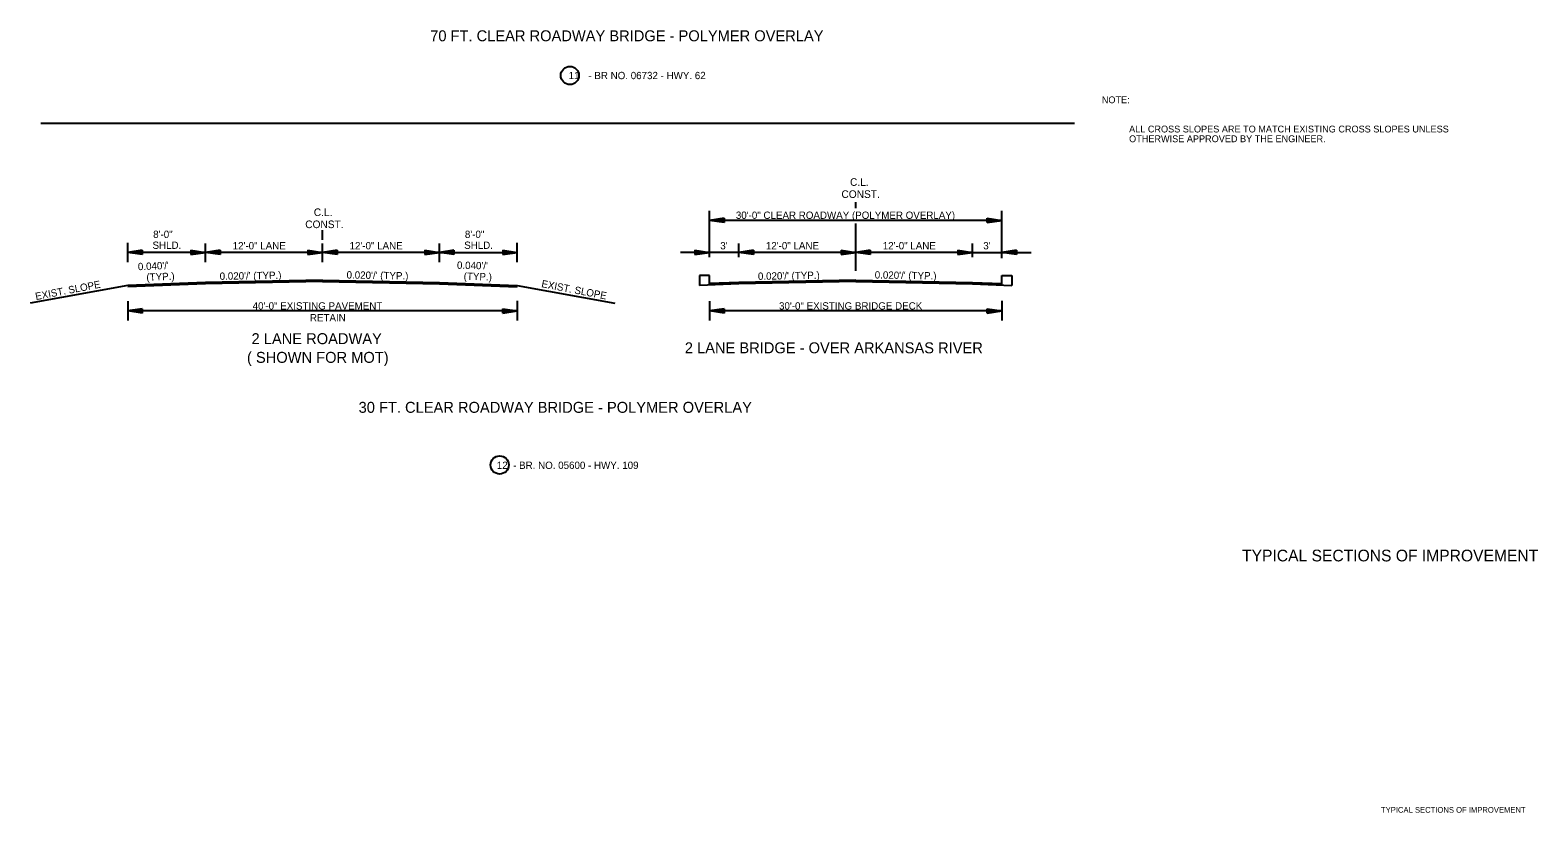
# Model space of a CAD drawing. Extents: x 550980 to 1930787, y -1972975 to 596640.
# Drawn here: x 550998 to 552546, y -1950690 to -1949887 of the extents above; entities that cross this region are included whole.
import ezdxf

# ---------------------------------------------------------------- set-up
doc = ezdxf.new("R2010")
doc.units = 0
for name, color, linetype in [('R_Border', 7, 'Continuous'), ('R_Border Notes', 7, 'Continuous'), ('R_Draft', 7, 'Continuous'), ('S_AREA_CALC', 7, 'Continuous')]:
    doc.layers.add(name, color=color, linetype=linetype)

# ---------------------------------------------------------------- blocks, each defined once
blk = doc.blocks.new('BPPOLY')
at = {"layer": 'R_Border'}
blk.add_circle((0, 0), 9.34, dxfattribs=at)

msp = doc.modelspace()

# ---------------------------------------------------------------- linework, layer by layer
at = {"layer": 'R_Border'}
for p, q in [((551009, -1949982.4), (552070.2, -1949982.4)), ((551685.4, -1950138.7), (551685.4, -1950148.8)), ((551695.6, -1950138.7), (551685.4, -1950138.7)), ((551695.6, -1950148.1), (551695.6, -1950138.7)), ((551995.6, -1950148.1), (551995.6, -1950138.7)), ((551995.6, -1950138.7), (552005.8, -1950138.7)), ((552005.8, -1950138.7), (552005.8, -1950148.8))]:
    msp.add_line(p, q, dxfattribs=at)
msp.add_circle((551480.1, -1950333.1), 9.34, dxfattribs=at)
at = {"layer": 'R_Draft'}
for p, q in [((551845.6, -1950069.4), (551845.6, -1950063.3)), ((551695.6, -1950119.7), (551695.6, -1950072.2)), ((551710.6, -1950079.9), (551695.6, -1950082.1)), ((551995.6, -1950082.1), (551695.6, -1950082.1)), ((551710.6, -1950084.4), (551695.6, -1950082.1)), ((551710.6, -1950080.2), (551698.1, -1950082.1)), ((551710.6, -1950084), (551698.1, -1950082.1)), ((551710.6, -1950080.6), (551700.7, -1950082.1)), ((551710.6, -1950083.6), (551700.7, -1950082.1)), ((551710.6, -1950081), (551703.2, -1950082.1)), ((551710.6, -1950083.2), (551703.2, -1950082.1)), ((551710.6, -1950081.4), (551705.7, -1950082.1)), ((551710.6, -1950082.9), (551705.7, -1950082.1)), ((551710.6, -1950081.8), (551708.2, -1950082.1)), ((551710.6, -1950082.5), (551708.2, -1950082.1)), ((551710.6, -1950079.9), (551710.6, -1950084.4)), ((551980.6, -1950079.9), (551995.6, -1950082.1)), ((551980.6, -1950084.4), (551980.6, -1950079.9)), ((551980.6, -1950080.2), (551993.1, -1950082.1)), ((551980.6, -1950080.6), (551990.5, -1950082.1)), ((551980.6, -1950081), (551988, -1950082.1)), ((551980.6, -1950081.4), (551985.5, -1950082.1)), ((551980.6, -1950081.8), (551983, -1950082.1)), ((551980.6, -1950084.4), (551995.6, -1950082.1)), ((551980.6, -1950082.9), (551985.5, -1950082.1)), ((551980.6, -1950083.6), (551990.5, -1950082.1)), ((551980.6, -1950084), (551993.1, -1950082.1)), ((551980.6, -1950083.2), (551988, -1950082.1)), ((551980.6, -1950082.5), (551983, -1950082.1)), ((551995.6, -1950120.9), (551995.6, -1950072.2)), ((551298.2, -1950101.9), (551298.2, -1950092)), ((551845.6, -1950105.8), (551845.6, -1950085.3)), ((551098.2, -1950125), (551098.2, -1950105)), ((551113.2, -1950112.7), (551098.2, -1950115)), ((551113.2, -1950113.1), (551100.7, -1950115)), ((551113.2, -1950112.7), (551113.2, -1950117.2)), ((551163.2, -1950112.7), (551178.2, -1950115)), ((551163.2, -1950112.7), (551163.2, -1950117.2)), ((551163.2, -1950113.1), (551175.6, -1950115)), ((551178.2, -1950125), (551178.2, -1950105.8)), ((551193.2, -1950112.7), (551178.2, -1950115)), ((551193.2, -1950113.1), (551180.7, -1950115)), ((551193.2, -1950112.7), (551193.2, -1950117.2)), ((551283.2, -1950112.7), (551298.2, -1950115)), ((551283.2, -1950112.7), (551283.2, -1950117.2)), ((551283.2, -1950113.1), (551295.6, -1950115)), ((551298.2, -1950125), (551298.2, -1950105.8)), ((551313.2, -1950112.7), (551298.2, -1950115)), ((551313.2, -1950113.1), (551300.7, -1950115)), ((551313.2, -1950112.7), (551313.2, -1950117.2)), ((551403.2, -1950112.7), (551418.2, -1950115)), ((551403.2, -1950112.7), (551403.2, -1950117.2)), ((551403.2, -1950113.1), (551415.6, -1950115)), ((551418.2, -1950125), (551418.2, -1950105.8)), ((551433.2, -1950112.7), (551418.2, -1950115)), ((551433.2, -1950113.1), (551420.7, -1950115)), ((551433.2, -1950112.7), (551433.2, -1950117.2)), ((551483.2, -1950112.7), (551498.2, -1950115)), ((551483.2, -1950112.7), (551483.2, -1950117.2)), ((551483.2, -1950113.1), (551495.6, -1950115)), ((551498.2, -1950125), (551498.2, -1950105)), ((551680.6, -1950112.7), (551695.6, -1950115)), ((551680.6, -1950112.7), (551680.6, -1950117.2)), ((551680.6, -1950113.1), (551693.1, -1950115)), ((551725.6, -1950119.7), (551725.6, -1950105.8)), ((551740.6, -1950112.7), (551725.6, -1950115)), ((551740.6, -1950113.1), (551728.1, -1950115)), ((551740.6, -1950112.7), (551740.6, -1950117.2)), ((551830.6, -1950112.7), (551845.6, -1950115)), ((551830.6, -1950112.7), (551830.6, -1950117.2)), ((551830.6, -1950113.1), (551843.1, -1950115)), ((551845.6, -1950133.7), (551845.6, -1950105.8)), ((551860.6, -1950112.7), (551845.6, -1950115)), ((551860.6, -1950113.1), (551848.1, -1950115)), ((551860.6, -1950112.7), (551860.6, -1950117.2)), ((551950.6, -1950112.7), (551965.6, -1950115)), ((551950.6, -1950112.7), (551950.6, -1950117.2)), ((551950.6, -1950113.1), (551963.1, -1950115)), ((551965.6, -1950119.7), (551965.6, -1950105.8)), ((552010.6, -1950112.7), (551995.6, -1950115)), ((552010.6, -1950113.1), (551998.1, -1950115)), ((552010.6, -1950112.7), (552010.6, -1950117.2)), ((551178.2, -1950115), (551098.2, -1950115)), ((551113.2, -1950117.2), (551098.2, -1950115)), ((551113.2, -1950116.8), (551100.7, -1950115)), ((551113.2, -1950113.5), (551103.2, -1950115)), ((551113.2, -1950116.5), (551103.2, -1950115)), ((551113.2, -1950113.8), (551105.7, -1950115)), ((551113.2, -1950116.1), (551105.7, -1950115)), ((551113.2, -1950114.2), (551108.3, -1950115)), ((551113.2, -1950115.7), (551108.3, -1950115)), ((551113.2, -1950114.6), (551110.8, -1950115)), ((551113.2, -1950115.3), (551110.8, -1950115)), ((551163.2, -1950113.5), (551173.1, -1950115)), ((551163.2, -1950113.8), (551170.6, -1950115)), ((551163.2, -1950114.2), (551168, -1950115)), ((551163.2, -1950114.6), (551165.5, -1950115)), ((551163.2, -1950117.2), (551178.2, -1950115)), ((551163.2, -1950115.7), (551168, -1950115)), ((551163.2, -1950116.5), (551173.1, -1950115)), ((551163.2, -1950116.8), (551175.6, -1950115)), ((551163.2, -1950116.1), (551170.6, -1950115)), ((551163.2, -1950115.3), (551165.5, -1950115)), ((551298.2, -1950115), (551178.2, -1950115)), ((551193.2, -1950117.2), (551178.2, -1950115)), ((551193.2, -1950116.8), (551180.7, -1950115)), ((551193.2, -1950113.5), (551183.2, -1950115)), ((551193.2, -1950116.5), (551183.2, -1950115)), ((551193.2, -1950113.8), (551185.7, -1950115)), ((551193.2, -1950116.1), (551185.7, -1950115)), ((551193.2, -1950114.2), (551188.3, -1950115)), ((551193.2, -1950115.7), (551188.3, -1950115)), ((551193.2, -1950114.6), (551190.8, -1950115)), ((551193.2, -1950115.3), (551190.8, -1950115)), ((551283.2, -1950113.5), (551293.1, -1950115)), ((551283.2, -1950113.8), (551290.6, -1950115)), ((551283.2, -1950114.2), (551288, -1950115)), ((551283.2, -1950114.6), (551285.5, -1950115)), ((551283.2, -1950117.2), (551298.2, -1950115)), ((551283.2, -1950115.7), (551288, -1950115)), ((551283.2, -1950116.5), (551293.1, -1950115)), ((551283.2, -1950116.8), (551295.6, -1950115)), ((551283.2, -1950116.1), (551290.6, -1950115)), ((551283.2, -1950115.3), (551285.5, -1950115)), ((551418.2, -1950115), (551298.2, -1950115)), ((551313.2, -1950117.2), (551298.2, -1950115)), ((551313.2, -1950116.8), (551300.7, -1950115)), ((551313.2, -1950113.5), (551303.2, -1950115)), ((551313.2, -1950116.5), (551303.2, -1950115)), ((551313.2, -1950113.8), (551305.7, -1950115)), ((551313.2, -1950116.1), (551305.7, -1950115)), ((551313.2, -1950114.2), (551308.3, -1950115)), ((551313.2, -1950115.7), (551308.3, -1950115)), ((551313.2, -1950114.6), (551310.8, -1950115)), ((551313.2, -1950115.3), (551310.8, -1950115)), ((551403.2, -1950113.5), (551413.1, -1950115)), ((551403.2, -1950113.8), (551410.6, -1950115)), ((551403.2, -1950114.2), (551408, -1950115)), ((551403.2, -1950114.6), (551405.5, -1950115)), ((551403.2, -1950117.2), (551418.2, -1950115)), ((551403.2, -1950115.7), (551408, -1950115)), ((551403.2, -1950116.5), (551413.1, -1950115)), ((551403.2, -1950116.8), (551415.6, -1950115)), ((551403.2, -1950116.1), (551410.6, -1950115)), ((551403.2, -1950115.3), (551405.5, -1950115)), ((551418.2, -1950115), (551498.2, -1950115)), ((551433.2, -1950117.2), (551418.2, -1950115)), ((551433.2, -1950116.8), (551420.7, -1950115)), ((551433.2, -1950113.5), (551423.2, -1950115)), ((551433.2, -1950116.5), (551423.2, -1950115)), ((551433.2, -1950113.8), (551425.7, -1950115)), ((551433.2, -1950116.1), (551425.7, -1950115)), ((551433.2, -1950114.2), (551428.3, -1950115)), ((551433.2, -1950115.7), (551428.3, -1950115)), ((551433.2, -1950114.6), (551430.8, -1950115)), ((551433.2, -1950115.3), (551430.8, -1950115)), ((551483.2, -1950113.5), (551493.1, -1950115)), ((551483.2, -1950113.8), (551490.6, -1950115)), ((551483.2, -1950114.2), (551488, -1950115)), ((551483.2, -1950114.6), (551485.5, -1950115)), ((551483.2, -1950117.2), (551498.2, -1950115)), ((551483.2, -1950115.7), (551488, -1950115)), ((551483.2, -1950116.5), (551493.1, -1950115)), ((551483.2, -1950116.8), (551495.6, -1950115)), ((551483.2, -1950116.1), (551490.6, -1950115)), ((551483.2, -1950115.3), (551485.5, -1950115)), ((551695.6, -1950115), (551665.6, -1950115)), ((551680.6, -1950113.5), (551690.5, -1950115)), ((551680.6, -1950113.8), (551688, -1950115)), ((551680.6, -1950114.2), (551685.5, -1950115)), ((551680.6, -1950114.6), (551683, -1950115)), ((551680.6, -1950117.2), (551695.6, -1950115)), ((551680.6, -1950115.7), (551685.5, -1950115)), ((551680.6, -1950116.5), (551690.5, -1950115)), ((551680.6, -1950116.8), (551693.1, -1950115)), ((551680.6, -1950116.1), (551688, -1950115)), ((551680.6, -1950115.3), (551683, -1950115)), ((551725.6, -1950115), (551695.6, -1950115)), ((551845.6, -1950115), (551725.6, -1950115)), ((551740.6, -1950117.2), (551725.6, -1950115)), ((551740.6, -1950116.8), (551728.1, -1950115)), ((551740.6, -1950113.5), (551730.7, -1950115)), ((551740.6, -1950116.5), (551730.7, -1950115)), ((551740.6, -1950113.8), (551733.2, -1950115)), ((551740.6, -1950116.1), (551733.2, -1950115)), ((551740.6, -1950114.2), (551735.7, -1950115)), ((551740.6, -1950115.7), (551735.7, -1950115)), ((551740.6, -1950114.6), (551738.2, -1950115)), ((551740.6, -1950115.3), (551738.2, -1950115)), ((551830.6, -1950113.5), (551840.5, -1950115)), ((551830.6, -1950113.8), (551838, -1950115)), ((551830.6, -1950114.2), (551835.5, -1950115)), ((551830.6, -1950114.6), (551833, -1950115)), ((551830.6, -1950117.2), (551845.6, -1950115)), ((551830.6, -1950115.7), (551835.5, -1950115)), ((551830.6, -1950116.5), (551840.5, -1950115)), ((551830.6, -1950116.8), (551843.1, -1950115)), ((551830.6, -1950116.1), (551838, -1950115)), ((551830.6, -1950115.3), (551833, -1950115)), ((551965.6, -1950115), (551845.6, -1950115)), ((551860.6, -1950117.2), (551845.6, -1950115)), ((551860.6, -1950116.8), (551848.1, -1950115)), ((551860.6, -1950113.5), (551850.7, -1950115)), ((551860.6, -1950116.5), (551850.7, -1950115)), ((551860.6, -1950113.8), (551853.2, -1950115)), ((551860.6, -1950116.1), (551853.2, -1950115)), ((551860.6, -1950114.2), (551855.7, -1950115)), ((551860.6, -1950115.7), (551855.7, -1950115)), ((551860.6, -1950114.6), (551858.2, -1950115)), ((551860.6, -1950115.3), (551858.2, -1950115)), ((551950.6, -1950113.5), (551960.5, -1950115)), ((551950.6, -1950113.8), (551958, -1950115)), ((551950.6, -1950114.2), (551955.5, -1950115)), ((551950.6, -1950114.6), (551953, -1950115)), ((551950.6, -1950117.2), (551965.6, -1950115)), ((551950.6, -1950115.7), (551955.5, -1950115)), ((551950.6, -1950116.5), (551960.5, -1950115)), ((551950.6, -1950116.8), (551963.1, -1950115)), ((551950.6, -1950116.1), (551958, -1950115)), ((551950.6, -1950115.3), (551953, -1950115)), ((551965.6, -1950115), (551995.6, -1950115)), ((552010.6, -1950117.2), (551995.6, -1950115)), ((551995.6, -1950115), (552025.6, -1950115)), ((552010.6, -1950116.8), (551998.1, -1950115)), ((552010.6, -1950113.5), (552000.7, -1950115)), ((552010.6, -1950116.5), (552000.7, -1950115)), ((552010.6, -1950113.8), (552003.2, -1950115)), ((552010.6, -1950116.1), (552003.2, -1950115)), ((552010.6, -1950114.2), (552005.7, -1950115)), ((552010.6, -1950115.7), (552005.7, -1950115)), ((552010.6, -1950114.6), (552008.2, -1950115)), ((552010.6, -1950115.3), (552008.2, -1950115)), ((551298.2, -1950143.3), (551178.2, -1950145.7)), ((551298.2, -1950143.6), (551178.2, -1950146)), ((551298.2, -1950143.9), (551178.2, -1950146.3)), ((551298.2, -1950144.2), (551178.2, -1950146.6)), ((551298.2, -1950143.3), (551418.2, -1950145.7)), ((551298.2, -1950143.6), (551418.2, -1950146)), ((551298.2, -1950143.9), (551418.2, -1950146.3)), ((551298.2, -1950144.2), (551418.2, -1950146.6)), ((551845.6, -1950143.3), (551725.6, -1950145.7)), ((551845.6, -1950143.6), (551725.6, -1950146)), ((551845.6, -1950143.9), (551725.6, -1950146.3)), ((551845.6, -1950144.2), (551725.6, -1950146.6)), ((551845.6, -1950143.3), (551965.6, -1950145.7)), ((551845.6, -1950143.6), (551965.6, -1950146)), ((551845.6, -1950143.9), (551965.6, -1950146.3)), ((551845.6, -1950144.2), (551965.6, -1950146.6)), ((551098.2, -1950148.9), (550998.1, -1950167.2)), ((551178.2, -1950145.7), (551098.2, -1950148.9)), ((551178.2, -1950146), (551098.2, -1950149.2)), ((551178.2, -1950146.3), (551098.2, -1950149.5)), ((551178.2, -1950146.6), (551098.2, -1950149.8)), ((551178.2, -1950146.9), (551098.2, -1950150.1)), ((551178.2, -1950147.2), (551098.2, -1950150.4)), ((551298.2, -1950144.5), (551178.2, -1950146.9)), ((551298.2, -1950144.8), (551178.2, -1950147.2)), ((551298.2, -1950144.9), (551178.2, -1950147.3)), ((551298.2, -1950144.5), (551418.2, -1950146.9)), ((551298.2, -1950144.8), (551418.2, -1950147.2)), ((551298.2, -1950144.9), (551418.2, -1950147.3)), ((551418.2, -1950145.7), (551498.2, -1950148.9)), ((551418.2, -1950146), (551498.2, -1950149.2)), ((551418.2, -1950146.3), (551498.2, -1950149.5)), ((551418.2, -1950146.6), (551498.2, -1950149.8)), ((551418.2, -1950146.9), (551498.2, -1950150.1)), ((551418.2, -1950147.2), (551498.1, -1950150.4)), ((551498.2, -1950148.9), (551598.2, -1950167.2)), ((551725.6, -1950147.2), (551685.4, -1950148.8)), ((551725.6, -1950145.7), (551695.6, -1950146.9)), ((551725.6, -1950146), (551695.6, -1950147.2)), ((551725.6, -1950146.3), (551695.6, -1950147.5)), ((551725.6, -1950146.6), (551695.6, -1950147.8)), ((551725.6, -1950146.9), (551695.6, -1950148.1)), ((551845.6, -1950144.5), (551725.6, -1950146.9)), ((551845.6, -1950144.8), (551725.6, -1950147.2)), ((551845.6, -1950144.9), (551725.6, -1950147.3)), ((551845.6, -1950144.5), (551965.6, -1950146.9)), ((551845.6, -1950144.8), (551965.6, -1950147.2)), ((551845.6, -1950144.9), (551965.6, -1950147.3)), ((551965.6, -1950145.7), (551995.6, -1950146.9)), ((551965.6, -1950146), (551995.6, -1950147.2)), ((551965.6, -1950146.3), (551995.6, -1950147.5)), ((551965.6, -1950146.6), (551995.6, -1950147.8)), ((551965.6, -1950146.9), (551995.6, -1950148.1)), ((551965.6, -1950147.2), (552005.8, -1950148.8)), ((551098.2, -1950164.9), (551098.2, -1950184.9)), ((551113.2, -1950172.7), (551098.2, -1950174.9)), ((551113.2, -1950177.2), (551098.2, -1950174.9)), ((551498.2, -1950174.9), (551098.2, -1950174.9)), ((551113.2, -1950173.1), (551100.7, -1950174.9)), ((551113.2, -1950176.8), (551100.7, -1950174.9)), ((551113.2, -1950173.4), (551103.2, -1950174.9)), ((551113.2, -1950176.4), (551103.2, -1950174.9)), ((551113.2, -1950173.8), (551105.7, -1950174.9)), ((551113.2, -1950176), (551105.7, -1950174.9)), ((551113.2, -1950174.2), (551108.3, -1950174.9)), ((551113.2, -1950175.7), (551108.3, -1950174.9)), ((551113.2, -1950174.6), (551110.8, -1950174.9)), ((551113.2, -1950175.3), (551110.8, -1950174.9)), ((551113.2, -1950172.7), (551113.2, -1950177.2)), ((551483.2, -1950172.7), (551498.2, -1950174.9)), ((551483.2, -1950177.2), (551483.2, -1950172.7)), ((551483.2, -1950173.1), (551495.6, -1950174.9)), ((551483.2, -1950173.4), (551493.1, -1950174.9)), ((551483.2, -1950173.8), (551490.6, -1950174.9)), ((551483.2, -1950174.2), (551488, -1950174.9)), ((551483.2, -1950174.6), (551485.5, -1950174.9)), ((551483.2, -1950177.2), (551498.2, -1950174.9)), ((551483.2, -1950175.7), (551488, -1950174.9)), ((551483.2, -1950176.4), (551493.1, -1950174.9)), ((551483.2, -1950176.8), (551495.6, -1950174.9)), ((551483.2, -1950176), (551490.6, -1950174.9)), ((551483.2, -1950175.3), (551485.5, -1950174.9)), ((551498.2, -1950164.7), (551498.2, -1950184.7)), ((551695.6, -1950164.9), (551695.6, -1950184.9)), ((551710.6, -1950172.7), (551695.6, -1950174.9)), ((551710.6, -1950177.2), (551695.6, -1950174.9)), ((551995.6, -1950174.9), (551695.6, -1950174.9)), ((551710.6, -1950173.1), (551698.1, -1950174.9)), ((551710.6, -1950176.8), (551698.1, -1950174.9)), ((551710.6, -1950173.4), (551700.7, -1950174.9)), ((551710.6, -1950176.4), (551700.7, -1950174.9)), ((551710.6, -1950173.8), (551703.2, -1950174.9)), ((551710.6, -1950176), (551703.2, -1950174.9)), ((551710.6, -1950174.2), (551705.7, -1950174.9)), ((551710.6, -1950175.7), (551705.7, -1950174.9)), ((551710.6, -1950174.6), (551708.2, -1950174.9)), ((551710.6, -1950175.3), (551708.2, -1950174.9)), ((551710.6, -1950172.7), (551710.6, -1950177.2)), ((551980.6, -1950172.7), (551995.6, -1950174.9)), ((551980.6, -1950177.2), (551980.6, -1950172.7)), ((551980.6, -1950173.1), (551993.1, -1950174.9)), ((551980.6, -1950173.4), (551990.5, -1950174.9)), ((551980.6, -1950173.8), (551988, -1950174.9)), ((551980.6, -1950174.2), (551985.5, -1950174.9)), ((551980.6, -1950174.6), (551983, -1950174.9)), ((551980.6, -1950177.2), (551995.6, -1950174.9)), ((551980.6, -1950175.7), (551985.5, -1950174.9)), ((551980.6, -1950176.4), (551990.5, -1950174.9)), ((551980.6, -1950176.8), (551993.1, -1950174.9)), ((551980.6, -1950176), (551988, -1950174.9)), ((551980.6, -1950175.3), (551983, -1950174.9)), ((551995.6, -1950164.7), (551995.6, -1950184.7))]:
    msp.add_line(p, q, dxfattribs=at)

# ---------------------------------------------------------------- block references
at = {"layer": 'R_Border'}
msp.add_blockref('BPPOLY', (551552.2, -1949933.3), dxfattribs=at)

# ---------------------------------------------------------------- texts
for s, height, p in [('70 FT. CLEAR ROADWAY BRIDGE - POLYMER OVERLAY', 11.25, (551408.8, -1949898.2)), ('11', 7.5, (551550.9, -1949937.1)), ('- BR NO. 06732 - HWY. 62', 7.5, (551571.2, -1949937.1)), ('( SHOWN FOR MOT)', 11.25, (551220.7, -1950228.3))]:
    msp.add_text(s, height=height, dxfattribs=at).set_placement(p)
msp.add_text('TYPICAL SECTIONS OF IMPROVEMENT', height=12, rotation=360, dxfattribs=at).set_placement((552242.3, -1950432.1))
at = {"layer": 'R_Border Notes'}
for s, p in [('NOTE: ', (552098.3, -1949961.8)), ('ALL CROSS SLOPES ARE TO MATCH EXISTING CROSS SLOPES UNLESS ', (552126.3, -1949991.8)), ('OTHERWISE APPROVED BY THE ENGINEER.', (552126.3, -1950001.8))]:
    msp.add_text(s, height=7, dxfattribs=at).set_placement(p)
at = {"layer": 'R_Draft'}
for s, height, p in [('CONST.', 7.8, (551831, -1950059)), ('C.L.', 7.8, (551839.8, -1950046.6)), ('CONST.', 7.8, (551280.5, -1950090)), ('C.L.', 7.8, (551289.3, -1950077.6)), ('30\'-0" CLEAR ROADWAY (POLYMER OVERLAY)', 7.5, (551722.6, -1950080.5)), ('8\'-0"', 7.5, (551124.4, -1950100.1)), ('8\'-0"', 7.5, (551444.4, -1950100.1)), ('SHLD.', 7.5, (551123.7, -1950111.3)), ('12\'-0" LANE', 7.5, (551206, -1950111.8)), ('12\'-0" LANE', 7.5, (551326, -1950111.8)), ('SHLD.', 7.5, (551443.7, -1950111.3)), ("3'", 7.5, (551706.6, -1950111.8)), ('12\'-0" LANE', 7.5, (551753.4, -1950111.8)), ('12\'-0" LANE', 7.5, (551873.4, -1950111.8)), ("3'", 7.5, (551976.6, -1950111.8)), ('40\'-0" EXISTING PAVEMENT ', 7.5, (551226.5, -1950173.6)), ('30\'-0" EXISTING BRIDGE DECK', 7.5, (551766.9, -1950173.6)), ('RETAIN', 7.5, (551285.3, -1950185.7)), ('2 LANE ROADWAY', 11.25, (551225.4, -1950209.1)), ('2 LANE BRIDGE - OVER ARKANSAS RIVER', 11.25, (551670.2, -1950218.5)), ('30 FT. CLEAR ROADWAY BRIDGE - POLYMER OVERLAY', 11.25, (551335.3, -1950279.6)), ('12  - BR. NO. 05600 - HWY. 109', 7.5, (551477.2, -1950337.2))]:
    msp.add_text(s, height=height, dxfattribs=at).set_placement(p)
for s, rotation, p in [("  0.040'/'", 2.448, (551103.3, -1950133.5)), ("0.040'/'", 358.6816, (551436.2, -1950131.7)), ('EXIST. SLOPE', 10.8829, (551004.1, -1950163.9)), (' (TYP.)', 2.448, (551114.8, -1950144.3)), ("0.020'/' (TYP.)", 0.9719, (551192.7, -1950143.1)), ("0.020'/' (TYP.)", 359.0281, (551322.9, -1950141.7)), ('(TYP.)', 358.6816, (551443.1, -1950143.1)), ('EXIST. SLOPE', 349.1171, (551522.5, -1950150.5)), ("0.020'/' (TYP.)", 0.9719, (551745.3, -1950143.1)), ("0.020'/' (TYP.)", 359.0281, (551865.1, -1950141.7))]:
    msp.add_text(s, height=7.5, rotation=rotation, dxfattribs=at).set_placement(p)
at = {"layer": 'S_AREA_CALC'}
msp.add_text('TYPICAL SECTIONS OF IMPROVEMENT', height=5.862, rotation=360, dxfattribs=at).set_placement((552384.9, -1950690.1))

doc.saveas('drawing.dxf')
